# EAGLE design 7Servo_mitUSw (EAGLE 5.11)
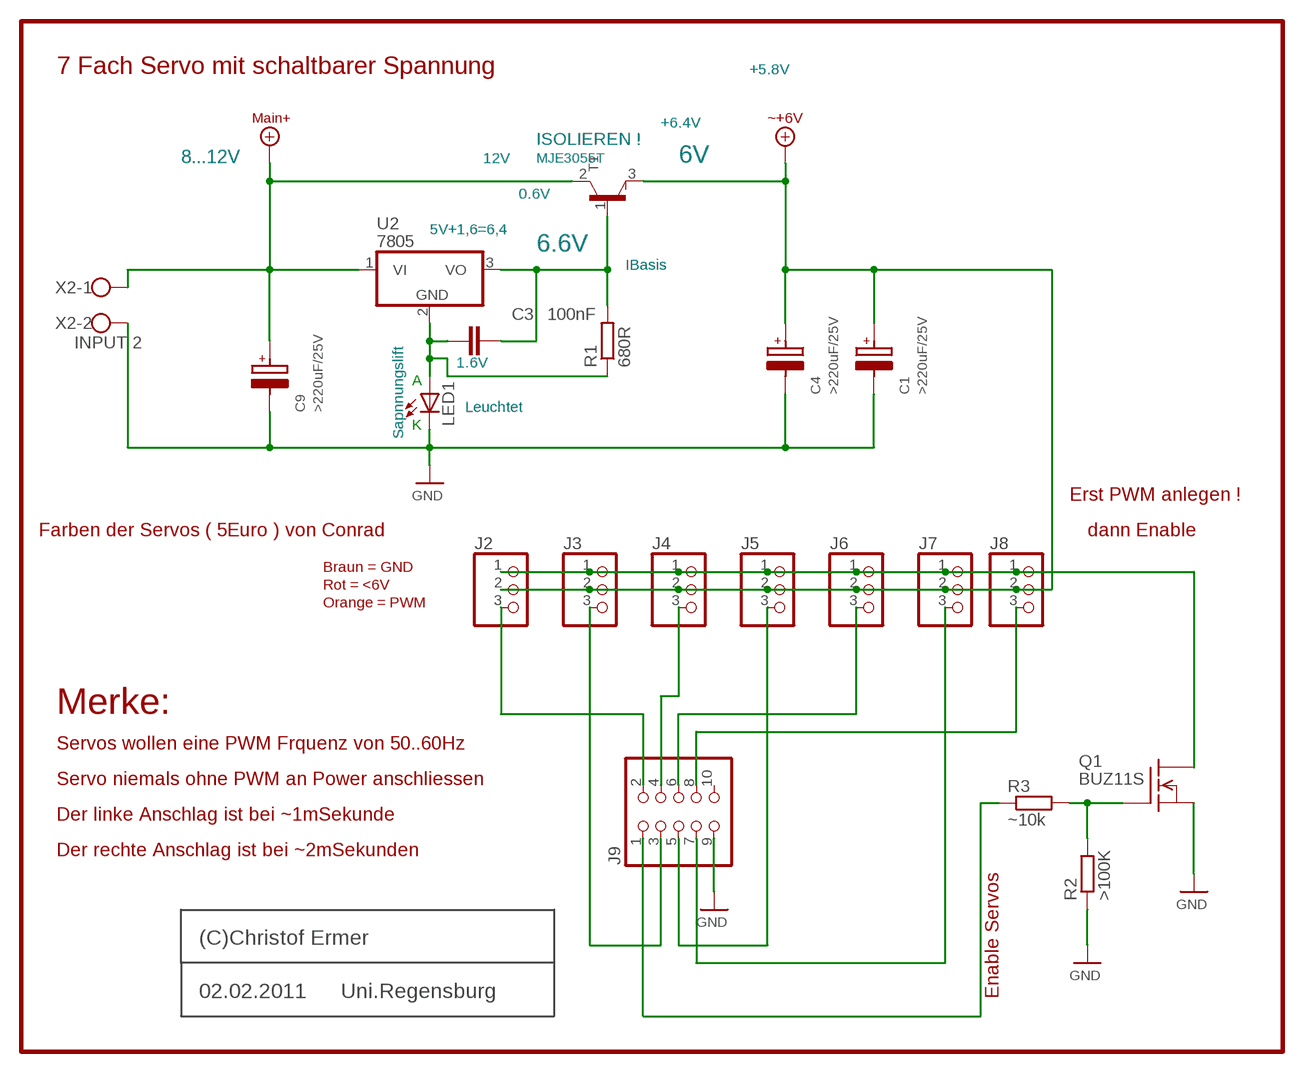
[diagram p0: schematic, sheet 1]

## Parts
C1  >220uF/25V  C10,5/RM5  [E5-10,5]
C3  100nF  C_5DICK  [C_050_025X075_DICK]
C4  >220uF/25V  C10,5/RM5  [E5-10,5]
C9  >220uF/25V  C10,5/RM5  [E5-10,5]
J2  PINHD-1X32L1R  [103_2L1R]
J3  PINHD-1X32L1R  [103_2L1R]
J4  PINHD-1X32L1R  [103_2L1R]
J5  PINHD-1X32L1R  [103_2L1R]
J6  PINHD-1X32L1R  [103_2L1R]
J7  PINHD-1X32L1R  [103_2L1R]
J8  PINHD-1X32L1R  [103_2L1R]
J9  PINHD-2X5OF  [2X05LONG]
LED1  LED5MM  [LED5MM]
Q1  BUZ11S  [TO220S@1]
R1  680R  R-EU_207/12_XL  [207/12_XL]
R2  >100K  R-EU_207/12_XL  [207/12_XL]
R3  ~10k  R-EU_207/12_XL  [207/12_XL]
T1  MJE3055_STEHEND  [TO220S]
U2  7805  78XXTO92  [TO_92]
X2  INPUT 2  W237-102  [W237-102]

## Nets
GND [W06]: C1.- C4.- C9.- J9.9 LED1.K(C) Q1.3(S) R2.1 X2.2
MAIN+: C9.+ T1.2(C) U2.1(VI) X2.1
N$1: C3.2 LED1.A R1.1 U2.2(GND)
N$2: J9.1 R3.1
N$3: J2.3 J9.2
N$4: J3.3 J9.3
N$5: J4.3 J9.4
N$6: J5.3 J9.5
N$7: J6.3 J9.6
N$8: J7.3 J9.7
N$9: J8.3 J9.8
N$10 [W06]: J2.1 J3.1 J4.1 J5.1 J6.1 J7.1 J8.1 Q1.2(D)
N$11: Q1.1(G) R2.2 R3.2
N$13: C3.1 R1.2 T1.1(B) U2.3(VO)
~6V: C1.+ C4.+ J2.2 J3.2 J4.2 J5.2 J6.2 J7.2 J8.2 T1.3(E)
Unconnected: J9.10

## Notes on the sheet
- 7 Fach Servo mit schaltbarer Spannung | +5.8V
- +6.4V
- ISOLIEREN !
- 8...12V | 12V | MJE3055T | 6V
- 0.6V
- 5V+1,6=6,4
- 6.6V
- IBasis
- 1.6V
- A
- Leuchtet
- K
- Sapnnungslift
- Erst PWM anlegen !
- Farben der Servos ( 5Euro ) von Conrad | dann Enable
- Braun = GND
- Rot = <6V
- Orange = PWM
- Merke:
- Servos wollen eine PWM Frquenz von 50..60Hz
- Servo niemals ohne PWM an Power anschliessen
- Der linke Anschlag ist bei ~1mSekunde
- Der rechte Anschlag ist bei ~2mSekunden
- (C)Christof Ermer
- 02.02.2011 | Uni.Regensburg | Enable Servos

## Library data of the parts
C1 C4 C9 = MY_ELKO_:C10,5/RM5: Elko Diameter:10,5 Pins:5mm
C3 = My_Kondensator:C_5
J2-J8 = My_Pinhead:PINHD-1X3: PIN HEADER
J9 = My_Pinhead:PINHD-2X5: PIN HEADER
LED1 = led:LED: LED
Q1 = MY_TRANS:BUZ11: N-Channel Enhancement MOSFET 50V; 30A; 0,040Ohm
R1-R3 = MY_Resistor:R-EU_: RESISTOR, European symbol
T1 = MY_TRANS:MJE3055_STEHEND
U2 = MYLINIC:78XX: Spannungsregler 78xx TO92
X2 = con-wago-500:W237-102: WAGO SCREW CLAMP

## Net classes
0 W05 def: width 0.508 mm, drill 0.61 mm, clearance 0.305 mm
1 W06: width 0.61 mm, drill 0.813 mm, clearance 0.305 mm
2 W08: width 0.813 mm, drill 1.016 mm, clearance 0.305 mm
3 W10: width 1.016 mm, drill 1.016 mm, clearance 0.305 mm

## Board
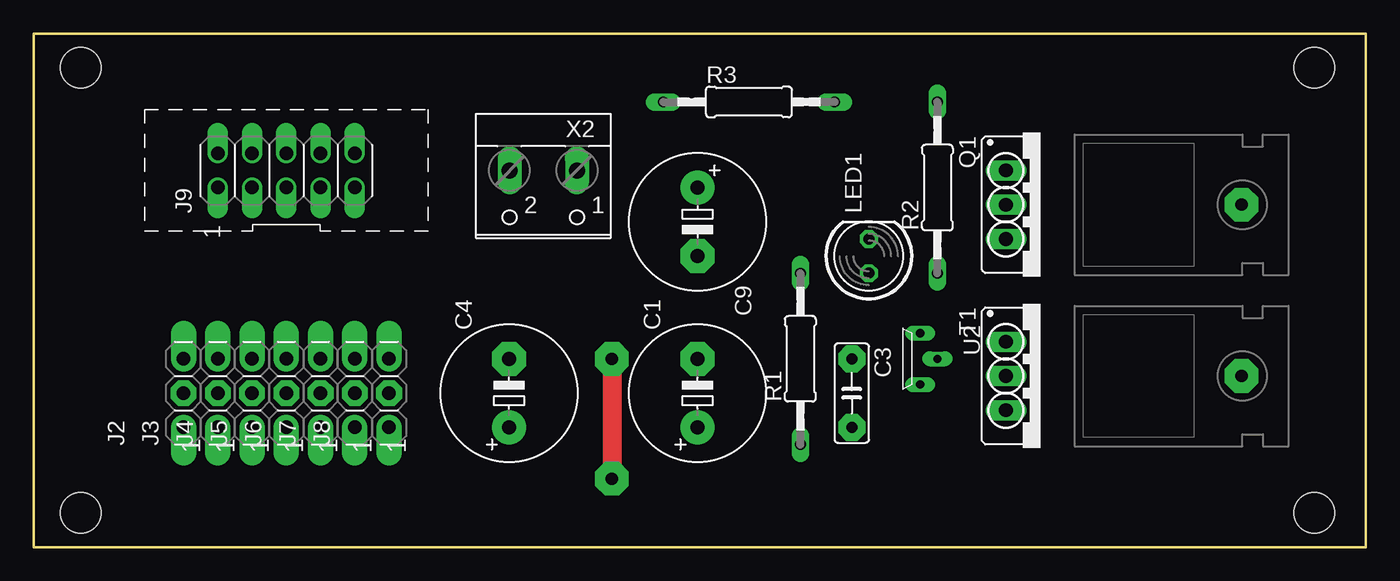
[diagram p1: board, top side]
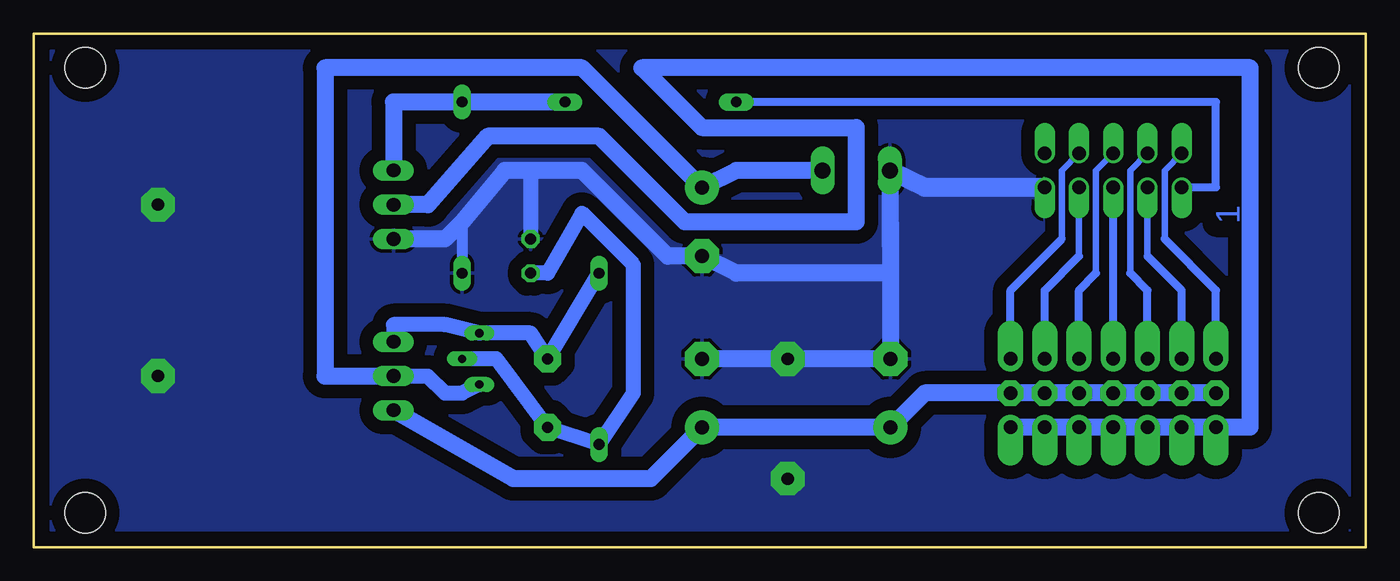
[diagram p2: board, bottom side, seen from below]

Size 98.73 x 38.08 mm. Coordinates in mm from the lower left corner, seen from the top.
Outline: 98.73,0 98.73,38.08 0,38.08 0,0 98.73,0
Copper layers (1*16): Top 0.035mm / dielectric 1.5mm / Bottom 0.035mm
Design rules "default": minimum track width 10mil, minimum drill 24mil, track to track 8mil, track to pad 8mil, pad to pad 8mil, via to via 8mil, smd to smd 8mil, copper to edge 40mil, drill to drill 8mil, minimum pad ring 10mil, minimum via ring 8mil, stop-mask expansion 4mil, vias tented up to drill 0mil, thermal gap 10mil
Holes 3 mm at 3.48,35.56 94.92,2.54 94.92,35.56 3.48,2.54

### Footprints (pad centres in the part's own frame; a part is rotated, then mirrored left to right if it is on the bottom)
E5-10,5 = drill 1.016 pad 2.54 round: + -2.54,0 | drill 1.016 pad 2.54 octagon: - 2.54,0
C_050_025X075_DICK = drill 0.813 pad 2 octagon: 1 -2.54,0; 2 2.54,0
103_2L1R = drill 1 pad 1.9 offset: 1 -2.54,0; 3 2.54,0 | drill 1 pad 1.9 octagon: 2 0,0
2X05LONG = drill 1 offset: 1 -5.08,-1.27; 2 -5.08,1.27; 3 -2.54,-1.27; 4 -2.54,1.27; 5 0,-1.27; 6 0,1.27; 7 2.54,-1.27; 8 2.54,1.27; 9 5.08,-1.27; 10 5.08,1.27
LED5MM = drill 0.813 octagon: A -1.27,0; K 1.27,0
TO220S@1 = drill 1.016 long: 1 -2.54,0; 2 0,0; 3 2.54,0
207/12_XL = drill 0.8 long: 1 -6.35,0; 2 6.35,0
TO220S = drill 1.016 long: 1 -2.54,0; 2 0,0; 3 2.54,0
TO_92 = drill 0.61 pad 1.092 long: 1 1.905,0; 2 0,1.27; 3 -1.905,0
W237-102 = drill 1.194 long: 1 -2.5,-1.27; 2 2.5,-1.27

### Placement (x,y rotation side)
C1  49.2,11.43 90 top
C3  60.63,11.43 270 top
C4  35.23,11.43 90 top
C9  49.2,24.13 270 top
J2  11.1,11.43 90 top
J3  13.64,11.43 90 top
J4  16.18,11.43 90 top
J5  18.72,11.43 90 top
J6  21.26,11.43 90 top
J7  23.8,11.43 90 top
J8  26.34,11.43 90 top
J9  18.72,27.94 0 top
LED1  61.9,21.59 90 top
Q1  72.06,25.4 270 top
R1  56.82,13.97 90 top
R2  66.98,26.67 90 top
R3  53.01,33.02 0 top
T1  72.06,12.7 270 top
U2  65.71,13.97 270 top
U$4  [TO220_LIEGGEHÄUSE]  82.22,25.4 270 top
U$7  [TO220_LIEGGEHÄUSE]  82.22,12.7 270 top
X2  37.77,26.67 180 top

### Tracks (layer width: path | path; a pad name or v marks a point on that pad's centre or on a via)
GND  (via drill 0.9 pad 2.5)
  Top 1.422: v42.85,13.97 v42.85,5.08
  Bottom 0.813: 66.98,24.13 R2.1
  Bottom 1.1: 61.9,27.94 LED1.K
  Bottom 1.27: C1.- v42.85,13.97 C4.- 35.23,16.51 X2.2 35.23,20.32 46.66,20.32 C9.- 51.74,21.59 58.09,27.94 61.9,27.94 63.81,27.94 66.98,24.13 68.25,22.86 Q1.3
  Bottom 1.422: J9.9 32.69,26.67 X2.2
  other vias: 89.52,25.4 89.52,12.7
  pour Bottom (isolate 1): 0.94,1.27 0.94,36.83 97.46,36.83 97.46,1.27
MAIN+
  Bottom 1.1: T1.2 69.52,12.7 68.25,11.43 66.98,11.43 U2.1
  Bottom 1.27: X2.1 46.66,27.94 C9.+ 58.09,35.56 77.14,35.56 77.14,12.7 T1.2
N$1
  Bottom 1.1: U2.2 64.44,13.97 C3.2 R1.1 54.28,11.43 54.28,20.95 58.09,24.77 60.63,20.32 LED1.A
N$2
  Bottom 0.61: J9.1 11.1,26.67 11.1,33.02 R3.1
N$3
  Bottom 0.5: J9.2 14.91,27.94 14.91,22.86
  Bottom 0.61: 14.91,22.86 11.1,19.05 J2.3
N$4
  Bottom 0.5: 16.18,21.59 J9.3
  Bottom 0.61: J3.3 13.64,19.05 16.18,21.59
N$5
  Bottom 0.5: J9.4 17.45,27.94 17.45,20.32
  Bottom 0.61: 17.45,20.32 16.18,19.05 J4.3
N$6
  Bottom 0.61: J5.3 J9.5
N$7
  Bottom 0.5: J9.6 19.99,27.94 19.99,20.32
  Bottom 0.61: 19.99,20.32 21.26,19.05 J6.3
N$8
  Bottom 0.5: 21.26,21.59 J9.7
  Bottom 0.61: J7.3 23.8,19.05 21.26,21.59
N$9
  Bottom 0.5: J9.8 22.53,27.94 22.53,22.86
  Bottom 0.61: 22.53,22.86 26.34,19.05 J8.3
N$10
  Bottom 1.27: J8.1 J7.1 J6.1 J5.1 J4.1 J3.1 J2.1 8.56,8.89 8.56,35.56 53.65,35.56 49.2,31.11 37.77,31.11 37.77,24.13 50.47,24.13 56.82,30.48 65.08,30.48 69.52,25.4 Q1.2
N$11
  Bottom 1.27: R3.2 R2.2 72.06,33.02 Q1.1
N$13
  Bottom 1.1: T1.1 72.06,16.51 68.25,16.51 U2.3 61.9,15.88 C3.1 R1.2
~6V
  Bottom 1.27: J2.2 J3.2 J4.2 J5.2 J6.2 J7.2 J8.2 32.69,11.43 C4.+ C1.+ 53.01,5.08 63.17,5.08 T1.3

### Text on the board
Bottom: 1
